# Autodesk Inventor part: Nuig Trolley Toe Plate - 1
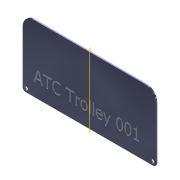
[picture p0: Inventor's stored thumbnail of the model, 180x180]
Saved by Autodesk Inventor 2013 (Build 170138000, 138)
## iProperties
Shininess: 64.0
Length Units: 11269
Angle Units: 11279
Time Units: 11290
Mass Units: 11286
Length Display Precision: 3
Angle Display Precision: 2
Manager: Alex
Created: 2002-08
Part Number: Nuig Trolley Toe Plate - 1
Document SubType Name: Modeling
Designer: kalamea
Density: 1 g/cm^3
Material: Generic
Density: 0.0
Volumn: 0.0
Area: 0.0
PropertySet Name: Model Information
Control State: 0
Master: False
Checked Out: False
DRAWING NUMBER: ME01-2007-PT
Author: kalamea
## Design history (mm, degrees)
sketch "Sketch1"
  geometry: L1 (-241.3, -120.65)-(241.3, -120.65); L2 (241.3, -120.65)-(241.3, 120.65); L3 (241.3, 120.65)-(-241.3, 120.65); L4 (-241.3, 120.65)-(-241.3, -120.65); 3 further points
  constraints: 8 end point, 2 midpoint, 2 parallel, 1 horizontal, 1 horizontal alignment, 1 perpendicular, 1 vertical alignment
  dimensions: "d0" = 482.6 distance of L2.end L3.end; "d1" = 241.3 distance of L3.end L1.start
extrude "Extrusion1" new body sketch "Sketch1" distance "d2" = 4.763; taper "d3" = 0 deg
sketch "Sketch2"
  geometry: L1 (-209.55, 120.65)-(209.55, 120.65) reference; L2 (241.3, -120.65)-(-241.3, -120.65) reference; L3 (0, -120.65)-(0, 120.65); 2 further points
  constraints: 2 end point, 2 midpoint, 1 horizontal alignment
  dimensions: "d6" = 228.6 distance from line of point (228.6, -107.95) L3; "d7" = 457.2 distance of point (-228.6, -107.95) point (228.6, -107.95); "d8" = 12.7 distance from line of L2 point (-228.6, -107.95)
hole "Hole1" sketch "Sketch2" at (228.6, -107.95), (-228.6, -107.95) diameter "d9" = 12.7; stored, may be unused: countersink angle "d13" = 82 deg, drill point angle "d15" = 118 deg; dims "d10" = 12.7, "d11" = 9.525, "d12" = 6.35, "d14" = 19.05
fillet "Fillet1" dims "d19" = 40
fillet "Fillet2" dims "d20" = 10
sketch "Sketch4"
  geometry: L1 (-201.489, -29.513)-(280.199, -29.513); L2 (280.199, -29.513)-(280.199, -125.749); L3 (280.199, -125.749)-(-201.489, -125.749); L4 (-201.489, -125.749)-(-201.489, -29.513)
  constraints: 2 other
emboss "Emboss2" sketch "Sketch4" dims "d21" = 1, "d22" = 0
body "Solid1"
